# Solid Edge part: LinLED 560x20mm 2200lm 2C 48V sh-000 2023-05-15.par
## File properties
Author: jaroslaw.przewlocki
Template: iso metric part.par
Last saved by: jaroslaw.przewlocki
Revision: 3
Application: Solid Edge
Gęstość: 0,000 kg/m^3
Dokładność: 0,990
Username: jaroslaw.przewlocki
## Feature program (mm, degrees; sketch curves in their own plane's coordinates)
body "unnamed Body 1"
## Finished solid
Body 1: solid body, 1590 faces, 4150 edges, 2708 vertices.
  Faces by surface: plane 1270, cylinder 164, torus 64, cone 50, spline 26, sphere 16
  Edges by curve: line 3474, curve on surface 356, circle 218, ellipse 66, spline 36
Bounding box of the edges (mm; curved faces can reach further): 559.600 x 20.000 x 4.450, from (-279.8, -10, -1) to (279.8, 10, 3.45).
Cylindrical faces by radius (mm): R0.2 x46, R0.2169 x6, R0.25 x32, R0.3373 x6, R0.4 x8, R0.4006 x2, R0.4008 x2, R0.525 x2, R0.6 x20, R1 x12, R1.1 x4, R1.1989 x2, R1.199 x2, R1.2 x10, R2.15 x10
Conical faces (half-angle, radius in mm at the cone's reference point): 0.398 deg R1.1964 x2, 0.4493 deg R1.1964 x2, 0.4746 deg R1.1948 x2, 0.4758 deg R1.1948 x2, 0.5 deg R0.5056 x4, 0.5 deg R1.0082 x4, 1 deg R0.5511 x2, 10 deg R0.2132 x4, 10 deg R0.4132 x4, 16.0099 deg R1.1053 x2, 16.1249 deg R1.1279 x2, 18.8604 deg R1.0669 x4, 19.5041 deg R0.5138 x2, 19.8244 deg R0.5099 x2, 27.363 deg R0.6214 x2, 40.6434 deg R0.5161 x2, 43.3309 deg R0.4892 x2, 45 deg R0.575 x2, 45 deg R0.625 x4
Toroidal faces (ring radius, tube radius in mm): R0.0958 r0.3997 x4, R0.1076 r0.4 x2, R0.1101 r0.4001 x2, R0.1217 r0.4 x2, R0.1234 r0.4 x2, R0.1626 r0.228 x2, R0.1634 r0.2287 x2, R0.3287 r0.2001 x2, R0.3684 r0.2151 x2, R0.3703 r0.4 x2, R0.3818 r0.2 x4, R0.4166 r0.3983 x2, R0.5981 r0.197 x2, R0.5982 r0.197 x2, R0.6009 r0.3968 x2, R0.6009 r0.3969 x2, R0.6227 r0.2 x2, R0.6235 r0.2 x2, R0.8 r0.2 x4, R0.8522 r0.3 x2, R0.9002 r0.2 x2, R0.9018 r0.2 x2, R0.9197 r0.223 x2, R0.9365 r0.2 x2, R0.9663 r0.2263 x2, R0.9665 r0.2263 x2, R1.429 r1.2 x2, R1.8741 r0.2175 x2, R1.9007 r0.2 x2
Spherical faces by radius (mm): R0.2 x12, R0.6 x4
Planar faces by outward normal: +x 154, +y 159, +z 217, -x 154, -y 161, -z 9, oblique 416
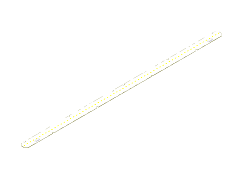
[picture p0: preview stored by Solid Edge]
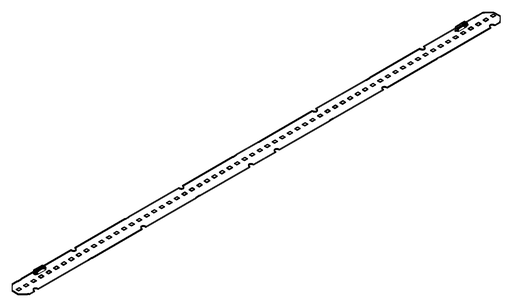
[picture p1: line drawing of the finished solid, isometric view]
